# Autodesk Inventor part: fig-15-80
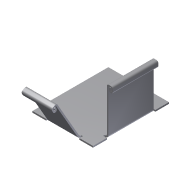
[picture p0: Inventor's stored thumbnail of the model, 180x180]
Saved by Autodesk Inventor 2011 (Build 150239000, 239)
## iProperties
Shininess: 77.0
Angle Display Precision: 2
Document Length Units: 11269
Document Angle Units: 11279
Document Time Units: 11290
Document Mass Units: 11283
Document Length Units Precision: 3
Document Angle Units Precision: 2
Compacted: True
Created: 2002-04
Part Number: fig-15-80
Document SubType Name: Sheet Metal
Density: 1 g/cm^3
Sheet Metal Rule: Default
Density: 0.0
Volumn: 0.0
Area: 0.0
PropertySet Name: Model Information
Control State: 0
Master: False
Checked Out: False
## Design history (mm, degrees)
node "Face1"
  sketch "Sketch1"
    geometry: L1 (-17.882, 11.882)-(2.118, 11.882); L2 (2.118, 11.882)-(2.118, -13.176); L3 (2.118, -13.176)-(-17.882, -13.176); L4 (-17.882, -13.176)-(-17.882, 11.882)
    constraints: 8 end point, 2 parallel, 1 horizontal, 1 perpendicular
    dimensions: "d17" = 20 distance of L2.end L3.end
node "Flange2"
node "Flange3"
feature "Hem8" dims "d82" = 0.5 (= BendReliefWidth), "d83" = 0.25 (= BendReliefDepth), "d84" = 1 (= MinimumRemnant), "d85" = 0.5 (= BendRadius), "d108" = 2 (= 4 x Thickness), "d109" = 0.25 (= 0.5 x Thickness), "d110" = 0.125 (= 0.5 x d109), "SeamGap" = 0.01, "Thickness" = 0.5
feature "Hem9" dims "d89" = 0.5 (= BendReliefWidth), "d90" = 0.25 (= BendReliefDepth), "d91" = 1 (= MinimumRemnant), "d92" = 0.5 (= BendRadius), "d111" = 2 (= 4 x Thickness), "d112" = 0.25 (= 0.5 x Thickness), "d113" = 0.125 (= 0.5 x d112), "SeamGap" = 0.01, "Thickness" = 0.5
body "Solid1"
face "Plate1" dims "Thickness" = 0.5
sketch "Sketch3"
  geometry: L1 (5, 0)-(20, 0); L2 (20, 0)-(20, 15); L3 (20, 15)-(5, 15); L4 (5, 15)-(5, 0)
  constraints: 8 end point
face "Plate3" dims "d6" = 15, "d7" = 90 deg, "d8" = 0.5 (= BendRadius), "d18" = 5, "d19" = 15, "Thickness" = 0.5, "MinimumRemnant" = 1 (= 2 x Thickness), "BendReliefWidth" = 0.5 (= Thickness)
bend "Bend2" dims "d6" = 15, "d7" = 90 deg, "d8" = 0.5 (= BendRadius), "d56" = 0.5 (= BendReliefWidth), "d57" = 0.25 (= BendReliefDepth), "d58" = 1 (= MinimumRemnant), "SeamGap" = 0.01, "Thickness" = 0.5, "MinimumRemnant" = 1 (= 2 x Thickness), "BendReliefWidth" = 0.5 (= Thickness), "TransitionRadius" = 0.5 (= BendRadius)
sketch "Sketch6"
  geometry: L1 (15, 0)-(5, 0); L2 (5, 0)-(5, 15); L3 (5, 15)-(15, 15); L4 (15, 15)-(15, 0)
  constraints: 8 end point
face "Plate4" dims "d20" = 5, "d21" = 10, "d23" = 15, "d24" = 60 deg, "d25" = 0.5 (= BendRadius), "Thickness" = 0.5, "MinimumRemnant" = 1 (= 2 x Thickness), "BendReliefWidth" = 0.5 (= Thickness)
bend "Bend3" dims "d22" = 0.5 (= BendRadius), "d23" = 15, "d24" = 60 deg, "d25" = 0.5 (= BendRadius), "d59" = 0.5 (= BendReliefWidth), "d60" = 0.25 (= BendReliefDepth), "d61" = 1 (= MinimumRemnant), "SeamGap" = 0.01, "Thickness" = 0.5, "MinimumRemnant" = 1 (= 2 x Thickness), "BendReliefWidth" = 0.5 (= Thickness)
sketch "Sketch12"
  geometry: L1 (0.433, 0.25)-(0, 0); L2 (-0.171, 0.046)-(-0.82, -0.329); L3 (-0.866, -0.5)-(-0.491, -1.15); L4 (-0.275, -1.025)-(-0.65, -0.375); L5 (-0.65, -0.375)-(-0.217, -0.125); L6 (-0.217, -0.125)-(0.158, -0.775); L7 (-0.924, -1.4)-(-1.299, -0.75); L8 (-1.07, 0.104)-(-0.421, 0.479); A1 r 0.125 centre (-0.108, -0.063) between (0, 0) and (-0.171, 0.046); A2 r 0.125 centre (-0.758, -0.438) between (-0.82, -0.329) and (-0.866, -0.5); A3 r 0.125 centre (-0.383, -1.087) between (-0.491, -1.15) and (-0.275, -1.025); A4 r 0.625 centre (-0.383, -1.087) between (-0.924, -1.4) and (0.158, -0.775); A5 r 0.625 centre (-0.758, -0.438) between (-1.07, 0.104) and (-1.299, -0.75); A6 r 0.625 centre (-0.108, -0.063) between (0.433, 0.25) and (-0.421, 0.479); 2 further points
  constraints: 16 end point, 12 point on circle
sketch "Sketch13"
  geometry: L1 (0.5, 0)-(0, 0); L2 (-0.125, 0.125)-(-0.875, 0.125); L3 (-1, 0)-(-1, -0.75); L4 (-0.75, -0.75)-(-0.75, 0); L5 (-0.75, 0)-(-0.25, 0); L6 (-0.25, 0)-(-0.25, -0.75); L7 (-1.5, -0.75)-(-1.5, 0); L8 (-0.875, 0.625)-(-0.125, 0.625); A1 r 0.125 centre (-0.125, 0) between (0, 0) and (-0.125, 0.125); A2 r 0.125 centre (-0.875, 0) between (-0.875, 0.125) and (-1, 0); A3 r 0.125 centre (-0.875, -0.75) between (-1, -0.75) and (-0.75, -0.75); A4 r 0.625 centre (-0.875, -0.75) between (-1.5, -0.75) and (-0.25, -0.75); A5 r 0.625 centre (-0.875, 0) between (-0.875, 0.625) and (-1.5, 0); A6 r 0.625 centre (-0.125, 0) between (0.5, 0) and (-0.125, 0.625); 2 further points
  constraints: 16 end point, 12 point on circle
other parameters: "BendRadius" = 0.5 (= Thickness), "BendReliefDepth" = 0.25 (= 0.5 x Thickness), "CornerReliefSize" = 2 (= 4 x Thickness), "d0" = 0.5 (= BendRadius), "d5" = 0.5 (= BendRadius), "d26" = 0.5 (= BendRadius), "d30" = 0.5 (= BendRadius), "JacobiRadiusSize" = 0.5 (= Thickness), "GapSize" = 0.5 (= Thickness)
